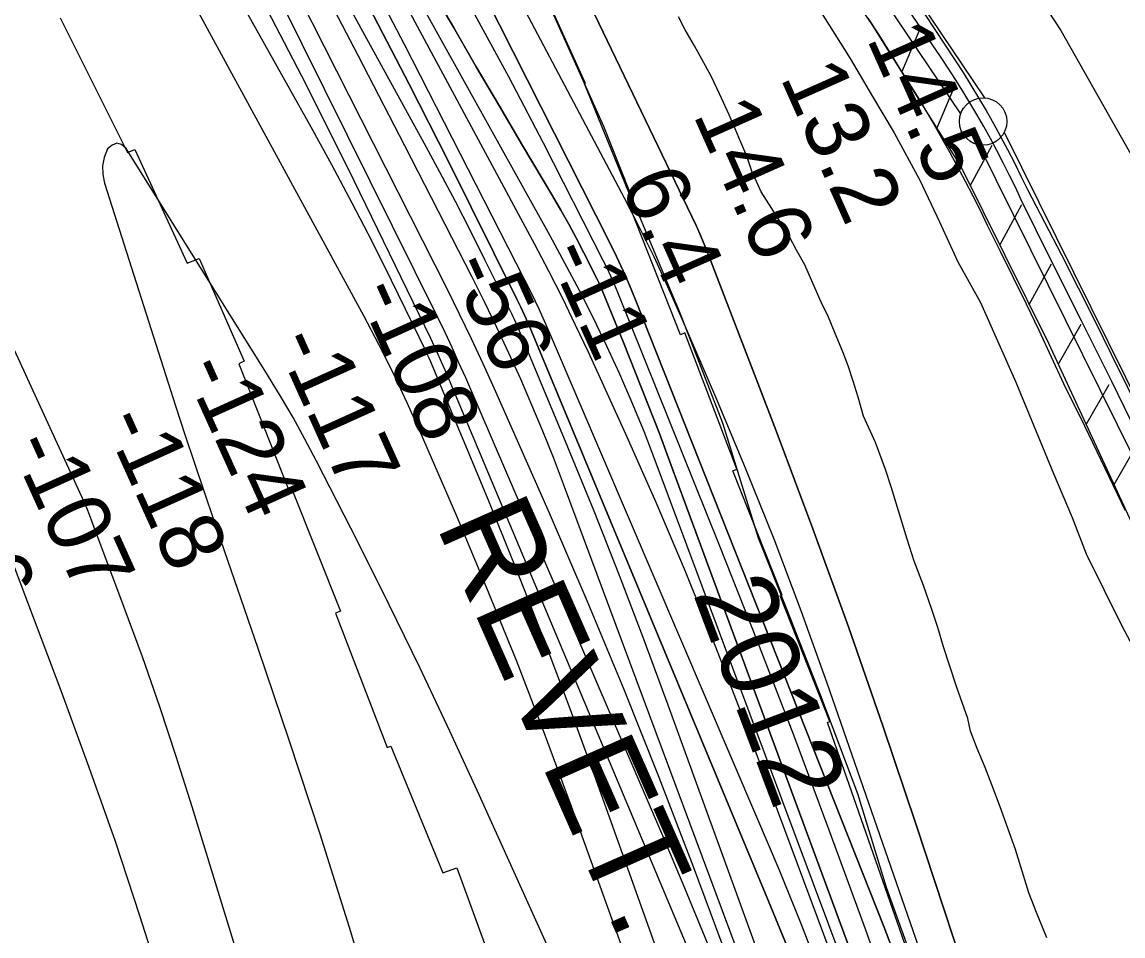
# Model space of a CAD drawing. Extents: x 3625074 to 3663148, y 511451 to 537151.
# Drawn here: x 3632002 to 3633164, y 529506 to 530470 of the extents above; entities that cross this region are included whole.
import ezdxf

# ---------------------------------------------------------------- set-up
doc = ezdxf.new("R2010")
doc.units = 0
for name, color, linetype in [('V-FLOD-BASE', 7, 'Continuous'), ('V-LEVE-TOET', 7, 'Continuous'), ('V-RIVR-EDGE', 7, 'Continuous'), ('V-RIVR-IDEN', 7, 'Continuous'), ('V-RIVR-RANG', 7, 'Continuous'), ('V-ROAD-CNTR', 7, 'Continuous'), ('V-RRAP-FSHR', 7, 'Continuous'), ('V-RRAP-RVMT', 7, 'Continuous'), ('V-RRAP-RVMT-IDEN', 7, 'Continuous'), ('V-SITE-VEGE', 7, 'Continuous'), ('V-SURV-LINE', 7, 'Continuous'), ('V-TOPO-DPTH', 7, 'Continuous'), ('V-TOPO-MAJR', 7, 'Continuous'), ('V-TOPO-MINR', 7, 'Continuous'), ('V-TOPO-WATR', 7, 'Continuous')]:
    doc.layers.add(name, color=color, linetype=linetype)

msp = doc.modelspace()

# ---------------------------------------------------------------- linework, layer by layer
at = {"layer": 'V-FLOD-BASE'}
msp.add_lwpolyline([(3633185.5, 530022.7), (3633152.3, 530090.5), (3633120.4, 530154.5), (3633088.5, 530218.4), (3633056.7, 530282.4), (3633050.6, 530295.5), (3633044.2, 530308.5), (3633037.8, 530321.4), (3633031.1, 530334.3), (3633024.3, 530347), (3633017.3, 530359.7), (3633010.1, 530372.2), (3633002.7, 530384.6), (3632995.2, 530397), (3632987.5, 530409.2), (3632979.6, 530421.3), (3632971.5, 530433.4), (3632824.8, 530647.7)], dxfattribs=at)
at = {"layer": 'V-LEVE-TOET'}
for points in [[(3632616.5, 531204.5), (3632687.2, 531083.7), (3632815, 530885.9), (3632945, 530696), (3633098.7, 530460.9), (3633162.2, 530348.5), (3633259.8, 530177.1), (3633278.3, 530140.5)], [(3632895, 530474.1), (3632906.4, 530456.4), (3632917.6, 530438.6), (3632928.7, 530420.6), (3632937.9, 530406.1), (3632947, 530391.5), (3632955.9, 530376.8), (3632964.6, 530362), (3632973.1, 530347.1), (3632981.5, 530332.1), (3632989.7, 530317), (3632997.8, 530301.8), (3633005.6, 530286.6), (3633013.3, 530271.2), (3633020.8, 530255.7), (3633034.7, 530228.1), (3633048.4, 530200.3), (3633061.9, 530172.5), (3633075.3, 530144.6), (3633088.5, 530116.6), (3633101.5, 530088.5), (3633123.4, 530043.9), (3633145.1, 529999.3), (3633166.4, 529954.4)]]:
    msp.add_lwpolyline(points, dxfattribs=at)
at = {"layer": 'V-RIVR-EDGE'}
msp.add_lwpolyline([(3633114.8, 528960.7), (3633105.7, 528999.3), (3633061.3, 529118.3), (3633043.1, 529182), (3633012.6, 529271), (3632990.8, 529339), (3632974.4, 529401), (3632947, 529466.6), (3632914.7, 529556.7), (3632884.3, 529655.5), (3632845.4, 529759.1), (3632809.4, 529850.5), (3632779.6, 529925.3), (3632741.9, 530046.7), (3632696.8, 530162.6), (3632652.4, 530269.4), (3632616.5, 530359.5), (3632551.2, 530504.9)], dxfattribs=at)
at = {"layer": 'V-ROAD-CNTR'}
msp.add_lwpolyline([(3632954.6, 530478.6), (3632986.9, 530429.9), (3632995.4, 530416.7), (3633003.7, 530403.4), (3633011.8, 530390), (3633019.8, 530376.5), (3633027.5, 530362.9), (3633035, 530349.2), (3633042.4, 530335.3), (3633049.6, 530321.4), (3633056.5, 530307.4), (3633063.3, 530293.2), (3633081.4, 530258.7), (3633099.3, 530224.1), (3633117, 530189.3), (3633134.5, 530154.5), (3633151.8, 530119.6), (3633168.9, 530084.6), (3633185.9, 530049.5), (3633199.3, 530023.2), (3633212.5, 529996.7), (3633225.5, 529970.2), (3633238.3, 529943.5), (3633250.9, 529916.8)], dxfattribs=at)
at = {"layer": 'V-RRAP-FSHR'}
for p, q in [((3632930.7, 530416.9), (3632949.8, 530461.9)), ((3632967.7, 530357.5), (3632986.8, 530402.5)), ((3633002.9, 530297.1), (3633026.3, 530340)), ((3633034.1, 530234.4), (3633057.4, 530277.3)), ((3633065.2, 530171.7), (3633088.6, 530214.6)), ((3633095.7, 530108.7), (3633120.2, 530151)), ((3633125.2, 530045.3), (3633149.7, 530087.5)), ((3633154.7, 529981.8), (3633179.2, 530024))]:
    msp.add_line(p, q, dxfattribs=at)
msp.add_lwpolyline([(3631673.9, 532278.1), (3631870.7, 531995.4), (3632026.6, 531760.3), (3632223.6, 531470.9), (3632511.5, 531032.6), (3632750.5, 530684.2), (3632899.2, 530467.4), (3632993.3, 530316.6), (3633085.4, 530131), (3633184.5, 529917.7), (3633256.5, 529764.5), (3633343, 529548.3), (3633478.2, 529185.2), (3633576.4, 528917.5), (3633718.3, 528535.8), (3633831.8, 528240.8)], dxfattribs=at)
at = {"layer": 'V-RRAP-RVMT'}
for p, q in [((3632597, 530405.1), (3632534.7, 530542.5)), ((3632042.6, 530474.2), (3632113.6, 530332.1)), ((3632595.9, 530404.5), (3632597, 530405.1)), ((3632649.6, 530272.7), (3632595.9, 530404.5)), ((3632113.6, 530332.1), (3632121.6, 530335.5)), ((3632121.6, 530335.5), (3632176.8, 530215.3)), ((3632645.5, 530270.8), (3632649.6, 530272.7)), ((3632697.1, 530140), (3632645.5, 530270.8)), ((3632176.8, 530215.3), (3632189.5, 530220.4)), ((3632189.5, 530220.4), (3632236.8, 530111.9)), ((3632701.8, 530141.8), (3632697.1, 530140)), ((3632756.7, 529998), (3632701.8, 530141.8)), ((3632236.8, 530111.9), (3632231.2, 530109.4)), ((3632231.2, 530109.4), (3632283.8, 529975.8)), ((3632752.4, 529996.3), (3632756.7, 529998)), ((3632804.7, 529865.2), (3632752.4, 529996.3)), ((3632283.8, 529975.8), (3632287.1, 529977)), ((3632287.1, 529977), (3632338.4, 529848.3)), ((3632802.5, 529864.3), (3632804.7, 529865.2)), ((3632854.8, 529731.9), (3632802.5, 529864.3)), ((3632338.4, 529848.3), (3632333.2, 529846.3)), ((3632333.2, 529846.3), (3632387.6, 529704.4)), ((3632852.4, 529731), (3632854.8, 529731.9)), ((3632938.8, 529483.2), (3632852.4, 529731)), ((3632387.6, 529704.4), (3632391.5, 529705.8)), ((3632391.5, 529705.8), (3632446.3, 529572.1)), ((3632446.3, 529572.1), (3632461.4, 529577.4)), ((3632461.4, 529577.4), (3632508.8, 529447.3))]:
    msp.add_line(p, q, dxfattribs=at)
at = {"layer": 'V-SITE-VEGE'}
for points in [[(3632827.9, 530508.8), (3632876.3, 530431.4), (3632899.8, 530391.3), (3632922.7, 530352.8), (3632949.9, 530302.9), (3632970.4, 530259.1), (3632990, 530216.9), (3633013.9, 530173.9), (3633051, 530090), (3633070.2, 530043.8), (3633091, 529993.5), (3633110.4, 529947), (3633125.3, 529908.7), (3633162.6, 529833.5), (3633182.9, 529795.1)], [(3633083.8, 529503.6), (3633073, 529530.4), (3633064.9, 529551.2), (3633050.8, 529596.7), (3633042.5, 529619.5), (3633034.7, 529642), (3633025.9, 529665.1), (3633018.7, 529683.5), (3633010.4, 529703.3), (3633003.1, 529721.7), (3633000.5, 529735), (3632988.9, 529767.9), (3632981.2, 529791.3), (3632974.6, 529810.8), (3632968.8, 529831), (3632962.6, 529850.2), (3632953.5, 529875.4), (3632943.7, 529901), (3632936.5, 529924.2), (3632919.6, 529979.4), (3632913.6, 529997.7), (3632902.9, 530026.1), (3632890.4, 530054.2), (3632884.8, 530073.9), (3632879.3, 530091), (3632874.1, 530107.2), (3632868.7, 530121.8), (3632860.3, 530141.1), (3632852.8, 530160.1), (3632846.6, 530171.9), (3632828.6, 530213.8), (3632819.8, 530229.3), (3632812.1, 530243.3), (3632803.5, 530257.3), (3632793.7, 530273.1), (3632782.3, 530290.8), (3632772.5, 530312.5), (3632767.3, 530328.4), (3632748.5, 530372.1), (3632738.3, 530394.1), (3632729.7, 530412.6), (3632712.1, 530444.8), (3632702.1, 530461.7), (3632695.3, 530475.4)]]:
    msp.add_lwpolyline(points, dxfattribs=at)
at = {"layer": 'V-SURV-LINE'}
for points in [[(3632604.3, 531004.1), (3633017.9, 530389.8)], [(3632993, 530373.1), (3632579.5, 530987.4)], [(3633038.9, 530353.6), (3633276.6, 529873.6)], [(3633249.7, 529860.3), (3633012, 530340.3)]]:
    msp.add_lwpolyline(points, dxfattribs=at)
msp.add_circle((3633016.6, 530364.9), 25, dxfattribs=at)
at = {"layer": 'V-TOPO-DPTH'}
for points in [[(3633071.3, 528849.1), (3633045.2, 528930.3), (3632933.7, 529275.1), (3632929.4, 529288.3), (3632924.9, 529301.5), (3632920.2, 529314.7), (3632915.4, 529327.7), (3632760.4, 529743), (3632732, 529816.8), (3632702.5, 529890.1), (3632671.5, 529962.9), (3632639.4, 530035.2), (3632600.1, 530121.4), (3632586.6, 530150.1), (3632572.8, 530178.7), (3632558.4, 530206.9), (3632543.7, 530235), (3632288.1, 530709.9)], [(3633071.3, 528849.1), (3633045.2, 528930.3), (3632933.7, 529275.1), (3632929.4, 529288.3), (3632924.9, 529301.5), (3632920.2, 529314.7), (3632915.4, 529327.7), (3632760.4, 529743), (3632732, 529816.8), (3632702.5, 529890.1), (3632671.5, 529962.9), (3632639.4, 530035.2), (3632600.1, 530121.4), (3632586.6, 530150.1), (3632572.8, 530178.7), (3632558.4, 530206.9), (3632543.7, 530235), (3632288.1, 530709.9)], [(3632557.7, 530580.1), (3632709.3, 530264.8), (3632714.1, 530254.5), (3632718.7, 530244.1), (3632723.1, 530233.6), (3632727.3, 530223.1), (3632798.1, 530038.4), (3632836.9, 529935.2), (3632874.6, 529831.6), (3632910.8, 529727.4), (3632946.1, 529622.9), (3633023.7, 529386.9), (3633031.2, 529364), (3633038.5, 529341.1), (3633045.8, 529318.1), (3633052.9, 529295.1), (3633238.3, 528691.6)], [(3632346.2, 530560.3), (3632405.5, 530446.6), (3632532, 530199.1), (3632539.9, 530183.3), (3632547.6, 530167.4), (3632554.9, 530151.3), (3632562, 530135.2), (3632777.6, 529631.4), (3632800.9, 529576), (3632823.6, 529520.4), (3632845.4, 529464.5), (3632866.7, 529408.4), (3632905, 529305.5), (3632906.8, 529300.7), (3632908.5, 529295.8), (3632910.1, 529290.9), (3632911.8, 529286), (3632940.1, 529198.2), (3632955.7, 529149.4), (3632971.3, 529100.5), (3632986.6, 529051.5), (3633001.7, 529002.5), (3633162.3, 528480)], [(3632346.2, 530560.3), (3632405.5, 530446.6), (3632532, 530199.1), (3632539.9, 530183.3), (3632547.6, 530167.4), (3632554.9, 530151.3), (3632562, 530135.2), (3632777.6, 529631.4), (3632800.9, 529576), (3632823.6, 529520.4), (3632845.4, 529464.5), (3632866.7, 529408.4), (3632905, 529305.5), (3632906.8, 529300.7), (3632908.5, 529295.8), (3632910.1, 529290.9), (3632911.8, 529286), (3632940.1, 529198.2), (3632955.7, 529149.4), (3632971.3, 529100.5), (3632986.6, 529051.5), (3633001.7, 529002.5), (3633162.3, 528480)], [(3632433.5, 530506), (3632457.6, 530464.3), (3632481.8, 530422.7), (3632506.2, 530381.2), (3632530.7, 530339.7), (3632562.3, 530286.4), (3632570.9, 530271.5), (3632579.3, 530256.6), (3632587.4, 530241.5), (3632595.3, 530226.3), (3632609, 530199.4), (3632610.8, 530195.7), (3632612.4, 530192), (3632637, 530131.9), (3632649.9, 530099.9), (3632662.6, 530067.8), (3632675, 530035.6), (3632687.1, 530003.2), (3632927.4, 529352.9), (3632935.5, 529330.5), (3632943.4, 529308), (3632951.1, 529285.4), (3632958.6, 529262.8), (3633198.4, 528521.9)], [(3633198.4, 528521.9), (3632958.6, 529262.8), (3632951.1, 529285.4), (3632943.4, 529308), (3632935.5, 529330.5), (3632927.4, 529352.9), (3632687.1, 530003.2), (3632675, 530035.6), (3632662.6, 530067.8), (3632649.9, 530099.9), (3632637, 530131.9), (3632612.4, 530192), (3632610.8, 530195.7), (3632609, 530199.4), (3632595.3, 530226.3), (3632587.4, 530241.5), (3632579.3, 530256.6), (3632570.9, 530271.5), (3632562.3, 530286.4), (3632530.7, 530339.7), (3632506.2, 530381.2), (3632481.8, 530422.7), (3632457.6, 530464.3), (3632433.5, 530506)], [(3632491.7, 530495.9), (3632622.5, 530237.5), (3632629.8, 530222.5), (3632636.8, 530207.4), (3632643.5, 530192.1), (3632649.8, 530176.7), (3632911.9, 529515.5), (3632924.3, 529483.4), (3632936.6, 529451.3), (3632948.4, 529419), (3632960, 529386.6), (3632971.3, 529354.1), (3632982.6, 529321.6), (3632993.7, 529289.1), (3633004.8, 529256.5), (3633006.9, 529250.3), (3633019, 529214.6), (3633031.1, 529178.9), (3633043.2, 529143.2), (3633055.4, 529107.6), (3633263.8, 528499.9)], [(3633263.8, 528499.9), (3633055.4, 529107.6), (3633043.2, 529143.2), (3633031.1, 529178.9), (3633019, 529214.6), (3633006.9, 529250.3), (3633004.8, 529256.5), (3632993.7, 529289.1), (3632982.6, 529321.6), (3632971.3, 529354.1), (3632960, 529386.6), (3632948.4, 529419), (3632936.6, 529451.3), (3632924.3, 529483.4), (3632911.9, 529515.5), (3632649.8, 530176.7), (3632643.5, 530192.1), (3632636.8, 530207.4), (3632629.8, 530222.5), (3632622.5, 530237.5), (3632491.7, 530495.9)], [(3633017.5, 528860.2), (3632995.4, 528931.4), (3632973.4, 529002.7), (3632951.4, 529074), (3632929.4, 529145.2), (3632910.7, 529205.8), (3632897.8, 529246.7), (3632884.6, 529287.5), (3632870.9, 529328.2), (3632856.8, 529368.7), (3632855.2, 529373.2), (3632839.7, 529415.8), (3632823.8, 529458.2), (3632807.2, 529500.4), (3632790.1, 529542.3), (3632540.1, 530143.6), (3632536.4, 530152.1), (3632532.6, 530160.7), (3632528.7, 530169.1), (3632524.6, 530177.6), (3632452, 530323.3), (3632410.9, 530404.3), (3632369, 530484.8)], [(3632369, 530484.8), (3632410.9, 530404.3), (3632452, 530323.3), (3632524.6, 530177.6), (3632528.7, 530169.1), (3632532.6, 530160.7), (3632536.4, 530152.1), (3632540.1, 530143.6), (3632790.1, 529542.3), (3632807.2, 529500.4), (3632823.8, 529458.2), (3632839.7, 529415.8), (3632855.2, 529373.2), (3632856.8, 529368.7), (3632870.9, 529328.2), (3632884.6, 529287.5), (3632897.8, 529246.7), (3632910.7, 529205.8), (3632929.4, 529145.2), (3632951.4, 529074), (3632973.4, 529002.7), (3632995.4, 528931.4), (3633017.5, 528860.2)]]:
    msp.add_lwpolyline(points, dxfattribs=at)
at = {"layer": 'V-TOPO-MAJR'}
for points in [[(3633088.3, 528519.1), (3632871.4, 529225.6), (3632863.3, 529251.5), (3632854.9, 529277.2), (3632846.1, 529302.8), (3632837.1, 529328.3), (3632684.3, 529749.2), (3632659, 529817.7), (3632632.9, 529885.8), (3632606, 529953.7), (3632578.3, 530021.2), (3632524.8, 530149.6), (3632523.4, 530152.8), (3632522, 530155.9), (3632520.6, 530159), (3632519.1, 530162.1), (3632491.2, 530218.4), (3632475.6, 530249.5), (3632459.7, 530280.5), (3632443.4, 530311.3), (3632426.8, 530341.9), (3632014, 531094)], [(3631920.6, 531048.5), (3632307.1, 530359.4), (3632329.1, 530319.4), (3632350.6, 530279.1), (3632371.4, 530238.5), (3632391.8, 530197.6), (3632428.4, 530122.6), (3632430.1, 530119), (3632431.7, 530115.4), (3632433.3, 530111.8), (3632434.9, 530108.2), (3632493.1, 529968.2), (3632523.2, 529894.3), (3632552.5, 529820.1), (3632580.6, 529745.5), (3632608, 529670.6), (3632742.3, 529294.3), (3632751.1, 529269.2), (3632759.7, 529244.1), (3632768, 529218.8), (3632776.2, 529193.6), (3633005.6, 528469.9)], [(3632629.5, 527747.7), (3632608.7, 527814.5), (3632493.6, 528191.1), (3632483.7, 528224.6), (3632474.1, 528258.1), (3632465, 528291.7), (3632456.2, 528325.5), (3632367, 528681.1), (3632350.5, 528746.4), (3632334, 528811.7), (3632317.3, 528877), (3632300.6, 528942.2), (3632274.7, 529042.7), (3632270.7, 529057.6), (3632266.6, 529072.6), (3632262.3, 529087.4), (3632257.9, 529102.3), (3632152, 529447.7), (3632126.9, 529526.7), (3632100.9, 529605.3), (3632073.4, 529683.5), (3632044.9, 529761.3), (3631993.6, 529897.6)]]:
    msp.add_lwpolyline(points, dxfattribs=at)
at = {"layer": 'V-TOPO-MINR'}
for points in [[(3632946.1, 528882), (3632917, 528978.6), (3632887.3, 529075), (3632833.9, 529244.8), (3632830.3, 529256.1), (3632826.5, 529267.3), (3632822.6, 529278.5), (3632818.5, 529289.6), (3632710.8, 529578.7), (3632674.8, 529672.8), (3632637.6, 529766.4), (3632598.8, 529859.3), (3632559, 529951.7), (3632500.9, 530083), (3632489, 530109.4), (3632476.8, 530135.6), (3632464.2, 530161.7), (3632451.3, 530187.6), (3632048.7, 530982.6)], [(3633139, 528925.7), (3633116.4, 528992.9), (3633094, 529060.1), (3633071.8, 529127.5), (3633049.7, 529194.8), (3633009.8, 529317.2), (3633007.7, 529323.4), (3633005.6, 529329.6), (3633003.5, 529335.8), (3633001.4, 529342), (3632851.9, 529772.5), (3632824.5, 529848.6), (3632796, 529924.3), (3632765.9, 529999.3), (3632734.7, 530073.9), (3632698.1, 530158.7), (3632684, 530190.4), (3632669.4, 530222), (3632654, 530253.1), (3632638.1, 530284), (3632282.3, 530956.3)], [(3633137, 528675.4), (3632944.7, 529269.6), (3632939, 529287), (3632933.1, 529304.4), (3632926.9, 529321.6), (3632920.6, 529338.8), (3632670.6, 530007.4), (3632658.8, 530037.9), (3632646.4, 530068.2), (3632633.3, 530098.2), (3632619.6, 530127.9), (3632605.3, 530157.4), (3632590.6, 530186.6), (3632575.3, 530215.6), (3632559.7, 530244.3), (3632231.2, 530835.2)], [(3633071.3, 528849.1), (3633045.2, 528930.3), (3632933.7, 529275.1), (3632929.4, 529288.3), (3632924.9, 529301.5), (3632920.2, 529314.7), (3632915.4, 529327.7), (3632760.4, 529743), (3632732, 529816.8), (3632702.5, 529890.1), (3632671.5, 529962.9), (3632639.4, 530035.2), (3632600.1, 530121.4), (3632586.6, 530150.1), (3632572.8, 530178.7), (3632558.4, 530206.9), (3632543.7, 530235), (3632288.1, 530709.9)], [(3632096.7, 530648.8), (3632362.7, 530160.2), (3632378.7, 530129.9), (3632394.1, 530099.4), (3632408.6, 530068.5), (3632422.6, 530037.3), (3632460.8, 529948.8), (3632492.7, 529872.9), (3632523.7, 529796.5), (3632553.3, 529719.7), (3632581.9, 529642.5), (3632722.3, 529252.7), (3632725.7, 529243.1), (3632729.1, 529233.4), (3632732.4, 529223.7), (3632735.5, 529214), (3632790.5, 529044), (3632820.5, 528949.1), (3632850, 528854)], [(3633049.2, 528439.9), (3632897.6, 528989.3), (3632884.6, 529035.3), (3632871.4, 529081.1), (3632857.6, 529126.7), (3632843.6, 529172.3), (3632818.3, 529252.6), (3632816.6, 529257.9), (3632814.8, 529263.2), (3632813, 529268.5), (3632811, 529273.8), (3632771.1, 529380.9), (3632748.8, 529439.5), (3632725.8, 529497.9), (3632702, 529555.9), (3632677.6, 529613.7), (3632470.6, 530094.4), (3632463.5, 530110.4), (3632456.3, 530126.4), (3632448.8, 530142.3), (3632441.1, 530158.1), (3632226.6, 530590.7)], [(3633238.3, 528691.6), (3633052.9, 529295.1), (3633045.8, 529318.1), (3633038.5, 529341.1), (3633031.2, 529364), (3633023.7, 529386.9), (3632946.1, 529622.9), (3632910.8, 529727.4), (3632874.6, 529831.6), (3632836.9, 529935.2), (3632798.1, 530038.4), (3632727.3, 530223.1), (3632723.1, 530233.6), (3632718.7, 530244.1), (3632714.1, 530254.5), (3632709.3, 530264.8), (3632557.7, 530580.1)], [(3632981.6, 528816.5), (3632849.5, 529237), (3632843.9, 529254.2), (3632838.2, 529271.4), (3632832.2, 529288.4), (3632826, 529305.5), (3632573.8, 529982.3), (3632563.1, 530010.3), (3632552.1, 530038.1), (3632540.5, 530065.7), (3632528.6, 530093.2), (3632516.2, 530120.5), (3632503.5, 530147.6), (3632490.3, 530174.5), (3632476.9, 530201.3), (3632406.3, 530339.1), (3632357, 530434.5), (3632307.4, 530529.7)], [(3632247.5, 530509.6), (3632297.5, 530413), (3632346.1, 530315.6), (3632433.3, 530136.2), (3632437.3, 530127.9), (3632441.1, 530119.6), (3632444.8, 530111.3), (3632448.4, 530102.9), (3632761.3, 529358.3), (3632768.1, 529341.8), (3632774.8, 529325.1), (3632781.3, 529308.5), (3632787.6, 529291.7), (3632793.7, 529274.9), (3632799.6, 529258), (3632805.2, 529240.9), (3632810.5, 529223.8), (3632815.7, 529206.6), (3632823.4, 529180.9), (3632830.9, 529155.1), (3632838.3, 529129.2), (3632845.7, 529103.3), (3633036.9, 528418.1)], [(3633198.4, 528521.9), (3632958.6, 529262.8), (3632951.1, 529285.4), (3632943.4, 529308), (3632935.5, 529330.5), (3632927.4, 529352.9), (3632687.1, 530003.2), (3632675, 530035.6), (3632662.6, 530067.8), (3632649.9, 530099.9), (3632637, 530131.9), (3632612.4, 530192), (3632610.8, 530195.7), (3632609, 530199.4), (3632595.3, 530226.3), (3632587.4, 530241.5), (3632579.3, 530256.6), (3632570.9, 530271.5), (3632562.3, 530286.4), (3632530.7, 530339.7), (3632506.2, 530381.2), (3632481.8, 530422.7), (3632457.6, 530464.3), (3632433.5, 530506)], [(3633017.5, 528860.2), (3632995.4, 528931.4), (3632973.4, 529002.7), (3632951.4, 529074), (3632929.4, 529145.2), (3632910.7, 529205.8), (3632897.8, 529246.7), (3632884.6, 529287.5), (3632870.9, 529328.2), (3632856.8, 529368.7), (3632855.2, 529373.2), (3632839.7, 529415.8), (3632823.8, 529458.2), (3632807.2, 529500.4), (3632790.1, 529542.3), (3632540.1, 530143.6), (3632536.4, 530152.1), (3632532.6, 530160.7), (3632528.7, 530169.1), (3632524.6, 530177.6), (3632452, 530323.3), (3632410.9, 530404.3), (3632369, 530484.8)], [(3633110.4, 528874.5), (3633074.8, 528979.4), (3633039.7, 529084.5), (3632984.8, 529250.1), (3632974, 529282.5), (3632963, 529314.8), (3632951.7, 529347), (3632940.3, 529379.2), (3632891, 529516.5), (3632854.3, 529617.1), (3632816.8, 529717.4), (3632778.2, 529817.2), (3632738.8, 529916.8), (3632631.2, 530184.4), (3632627.6, 530193), (3632623.8, 530201.6), (3632619.8, 530210), (3632615.7, 530218.4), (3632552.8, 530342.2), (3632516.2, 530412), (3632478.4, 530481)], [(3632102.3, 530342), (3632097.4, 530340.1), (3632092.6, 530336), (3632089.2, 530327.1), (3632087.3, 530318.2), (3632087.6, 530309), (3632089.3, 530299.7), (3632164.5, 530065), (3632174.3, 530034.7), (3632184.3, 530004.4), (3632194.5, 529974.2), (3632204.8, 529944.1), (3632251.3, 529809.2), (3632284.3, 529711.4), (3632316.5, 529613.4), (3632347.5, 529514.9), (3632377.6, 529416.2)], [(3632787.1, 528916.4), (3632761.9, 528992.1), (3632735.8, 529067.5), (3632706.2, 529151), (3632693.8, 529184.3), (3632681, 529217.4), (3632667.3, 529250.2), (3632653, 529282.7), (3632484.8, 529654.6), (3632453.8, 529721.8), (3632422.2, 529788.7), (3632389.7, 529855.1), (3632356.6, 529921.3), (3632313.2, 530006.4), (3632301, 530029.6), (3632288.4, 530052.6), (3632275.2, 530075.2), (3632261.6, 530097.6), (3632112.4, 530336.6), (3632107.4, 530340.5), (3632102.3, 530342)], [(3632395.2, 528913.6), (3632386.5, 528951.2), (3632377.3, 528988.7), (3632367.8, 529026.2), (3632352.4, 529084.5), (3632350.2, 529092.7), (3632348, 529100.9), (3632345.6, 529109), (3632343.2, 529117.1), (3632182, 529641.8), (3632165.2, 529694.8), (3632147.7, 529747.5), (3632129.4, 529800), (3632110.3, 529852.2), (3632076.2, 529943.3), (3632073.7, 529949.8), (3632071.1, 529956.2), (3632068.4, 529962.6), (3632065.6, 529968.9), (3631901.4, 530325.7)]]:
    msp.add_lwpolyline(points, dxfattribs=at)
at = {"layer": 'V-TOPO-WATR'}
msp.add_lwpolyline([(3633263.8, 528499.9), (3633055.4, 529107.6), (3633043.2, 529143.2), (3633031.1, 529178.9), (3633019, 529214.6), (3633006.9, 529250.3), (3633004.8, 529256.5), (3632993.7, 529289.1), (3632982.6, 529321.6), (3632971.3, 529354.1), (3632960, 529386.6), (3632948.4, 529419), (3632936.6, 529451.3), (3632924.3, 529483.4), (3632911.9, 529515.5), (3632649.8, 530176.7), (3632643.5, 530192.1), (3632636.8, 530207.4), (3632629.8, 530222.5), (3632622.5, 530237.5), (3632491.7, 530495.9)], dxfattribs=at)

# ---------------------------------------------------------------- texts
at = {"layer": 'V-RIVR-IDEN'}
msp.add_text('2012', height=83, rotation=290.6822, dxfattribs=at).set_placement((3632710, 529867.3))
at = {"layer": 'V-RIVR-RANG'}
for s, rotation, p in [('14.5', 294.0083, (3632893.2, 530452.6)), ('13.2', 294.0083, (3632802, 530411.6)), ('14.6', 294.0083, (3632710, 530372.4)), ('6.4', 294.0083, (3632633, 530299.4)), ('-11', 294.2949, (3632555.8, 530226.5)), ('-56', 294.2949, (3632452.2, 530212.7)), ('-108', 294.2949, (3632354.9, 530185.3)), ('-117', 294.2949, (3632268.9, 530132.8)), ('-124', 294.2949, (3632171.9, 530104.6)), ('-118', 294.2949, (3632087.3, 530049)), ('-107', 294.2949, (3631989.1, 530023.5)), ('-96', 294.2949, (3631905.6, 529965.3))]:
    msp.add_text(s, height=67, rotation=rotation, dxfattribs=at).set_placement(p)
at = {"layer": 'V-RRAP-RVMT-IDEN'}
msp.add_text('REVET.', height=100, rotation=293.8401, dxfattribs=at).set_placement((3632438.8, 529939.4))

doc.saveas('drawing.dxf')
